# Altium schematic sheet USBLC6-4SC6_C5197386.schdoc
size 127 x 101 mm
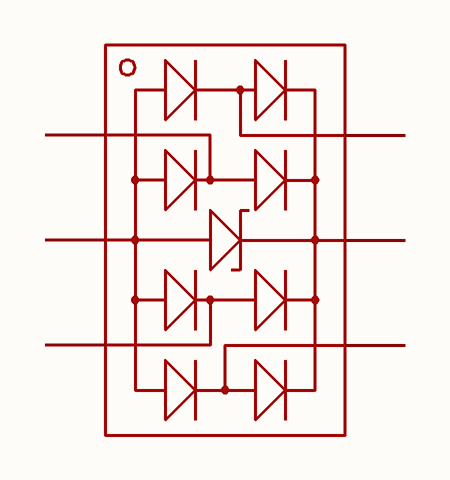
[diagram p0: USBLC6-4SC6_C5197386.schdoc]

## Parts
U?  usblc6-4sc6_c5197386  [SOT-23-6_L2.9-W1.6-P0.95-LS2.8-BL]  (value not drawn)

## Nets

Not connected (* = marked no-connect by the designer): U? 1 2 3 4 5 6

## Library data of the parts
U? = usblc6-4sc6_c5197386: 极性:单向;反向截止电压(Vrwm):5V;钳位电压:15V;峰值脉冲电流(Ipp):4.7A@8/20us;峰值脉冲功率(Ppp):300W@8/20us;击穿电压:6V;; Manufacturer: TECH PUBLIC(台舟); AddInBom: yes; ModelId: 18da8f6c14a34920b3e136b5c401a119; ModelName: SOT-23-6_L2.9-W1.6-H1.5-LS2.8-P0.95; ModelTransform: 110.236,113.364,0,90,0,0,0.0005,0.0005,0; Polarity: 单向; Reverse Stand-Off Voltage (Vrwm): 5V; Clamping Voltage: 15V; Voltage - Breakdown: 6V; Reverse Leakage Current (Ir): 80nA; Number of Channels: 四路; level of protection: IEC 61000-4-2；IEC 61000-4-4；IEC 61000-4-5; Junction Capacitance: 0.3pF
